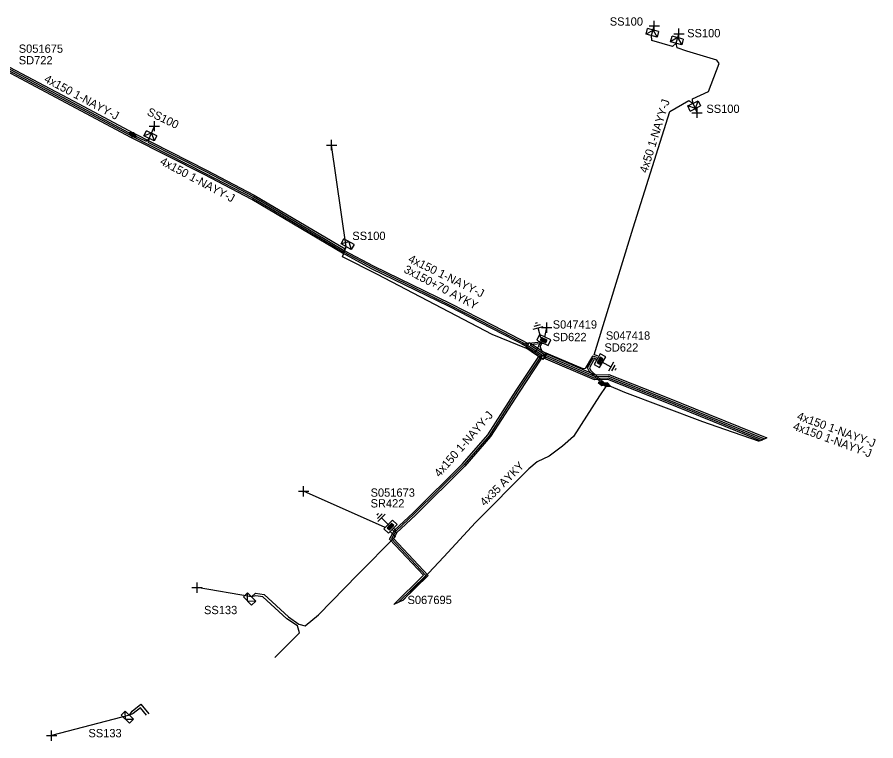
# Model space of a CAD drawing. Extents: x -737417 to -734469, y -1145580 to -1142703.
# Drawn here: x -736452.8 to -736349.1, y -1144284.4 to -1144197 of the extents above; entities that cross this region are included whole.
import ezdxf

# ---------------------------------------------------------------- set-up
doc = ezdxf.new("R2010")
doc.units = 0
for name, color, linetype in [('Vrstva 1', 7, 'Continuous'), ('Vrstva 14', 7, 'Continuous'), ('Vrstva 15', 7, 'Continuous'), ('Vrstva 19', 7, 'Continuous'), ('Vrstva 20', 7, 'Continuous'), ('Vrstva 28', 7, 'Continuous'), ('Vrstva 29', 7, 'Continuous'), ('Vrstva 30', 7, 'Continuous'), ('Vrstva 31', 7, 'Continuous'), ('Vrstva 33', 7, 'Continuous'), ('Vrstva 34', 7, 'Continuous'), ('Vrstva 4', 7, 'Continuous'), ('Vrstva 5', 7, 'Continuous'), ('Vrstva 59', 7, 'Continuous'), ('Vrstva 6', 7, 'Continuous'), ('Vrstva 8', 7, 'Continuous'), ('Vrstva 9', 7, 'Continuous')]:
    doc.layers.add(name, color=color, linetype=linetype)

# ---------------------------------------------------------------- blocks, each defined once
blk = doc.blocks.new('NN870')
at = {"layer": 'Vrstva 4'}
for points in [[(0, -0.25), (0.5, 0), (0, 0.25), (-0.5, 0), (0, -0.25)], [(0.37, 0), (0, 0.19), (-0.36, 0), (0, -0.19), (0.37, 0)], [(0.24, 0), (0, 0.12), (-0.25, 0), (0, -0.12), (0.24, 0)], [(0.12, 0), (0, 0.06), (-0.13, 0), (0, -0.06), (0.12, 0)]]:
    blk.add_lwpolyline(points, dxfattribs=at)
blk = doc.blocks.new('NN800')
at = {"layer": 'Vrstva 1'}
for points in [[(-0.44, 0.44), (0.44, -0.44)], [(-0.44, -0.44), (0.44, 0.44)]]:
    blk.add_lwpolyline(points, dxfattribs=at)
blk = doc.blocks.new('NN620')
at = {"layer": 'Vrstva 8'}
for points in [[(0.75, 0), (-0.75, 0)], [(-0.75, 0), (-0.75, -0.75)], [(0.75, -0.75), (0.75, 0)], [(-0.75, -0.75), (0.75, -0.75)], [(0.37, -0.18), (-0.38, -0.18)], [(-0.38, -0.18), (-0.38, -0.56)], [(-0.38, -0.56), (0.37, -0.56)], [(0.32, -0.23), (-0.33, -0.23)], [(-0.33, -0.23), (-0.33, -0.51)], [(-0.33, -0.51), (0.32, -0.51)], [(0.27, -0.27), (-0.28, -0.27)], [(-0.28, -0.27), (-0.28, -0.46)], [(-0.28, -0.46), (0.27, -0.46)], [(0.23, -0.32), (-0.23, -0.32)], [(-0.23, -0.32), (-0.23, -0.42)], [(-0.23, -0.42), (0.23, -0.42)], [(-0.19, -0.37), (0.19, -0.37)], [(0.23, -0.42), (0.23, -0.32)], [(0.27, -0.46), (0.27, -0.27)], [(0.32, -0.51), (0.32, -0.23)], [(0.37, -0.56), (0.37, -0.18)]]:
    blk.add_lwpolyline(points, dxfattribs=at)
blk = doc.blocks.new('NN630')
at = {"layer": 'Vrstva 9'}
for points in [[(0, -0.7), (-0.7, 0)], [(-0.7, -0.7), (-0.7, 0), (0.7, 0), (0.7, -0.7)], [(-0.7, -0.7), (0.7, -0.7)], [(0, -0.7), (0.7, 0)]]:
    blk.add_lwpolyline(points, dxfattribs=at)
blk = doc.blocks.new('NN810')
at = {"layer": 'Vrstva 14'}
for points in [[(0, -0.64), (0, -1.89)], [(0.63, -1.89), (-0.62, -1.89)], [(0.39, -2.2), (-0.4, -2.2)], [(0, -2.52), (-0.12, -2.52)], [(0.14, -2.52), (0, -2.52)]]:
    blk.add_lwpolyline(points, dxfattribs=at)

msp = doc.modelspace()

# ---------------------------------------------------------------- linework, layer by layer
at = {"layer": 'Vrstva 20'}
for points in [[(-736438.71, -1144211.02), (-736429.92, -1144215.47), (-736424.15, -1144218.48), (-736413.18, -1144224.99), (-736413.48, -1144225.51), (-736424.45, -1144219), (-736430.2, -1144216.01), (-736438.99, -1144211.56), (-736446.3, -1144207.66), (-736455.4, -1144202.85), (-736455.12, -1144202.32), (-736446.02, -1144207.12)], [(-736409.78, -1144227.02), (-736400.45, -1144231.59), (-736395.26, -1144234.23), (-736391.05, -1144236.42), (-736391.23, -1144236.77), (-736395.44, -1144234.59), (-736400.62, -1144231.95), (-736409.97, -1144227.38), (-736413.47, -1144225.51), (-736413.29, -1144225.16)], [(-736390.92, -1144236.27), (-736388.86, -1144237.66), (-736389.31, -1144238.32), (-736391.36, -1144236.93)], [(-736363.01, -1144248.14), (-736374.5, -1144243.49), (-736381.43, -1144240.73), (-736383.05, -1144240.78), (-736389.16, -1144238.18), (-736388.92, -1144237.62), (-736382.93, -1144240.18), (-736381.33, -1144240.13), (-736374.28, -1144242.93), (-736362.25, -1144247.8)], [(-736392.51, -1144242.06), (-736389.79, -1144237.97), (-736389.11, -1144237.71), (-736388.97, -1144238.09), (-736389.53, -1144238.29), (-736392.17, -1144242.28), (-736395.6, -1144247.65), (-736398.7, -1144251.21), (-736404.69, -1144257.12), (-736406.95, -1144259.26), (-736407.23, -1144258.96), (-736404.97, -1144256.84), (-736399, -1144250.93), (-736395.92, -1144247.41)], [(-736407.3, -1144267.92), (-736403.7, -1144264.39), (-736407.83, -1144260.02), (-736407.27, -1144259.01), (-736406.92, -1144259.21), (-736407.33, -1144259.96), (-736403.14, -1144264.41), (-736406.25, -1144267.45)]]:
    msp.add_lwpolyline(points, close=True, dxfattribs=at)
at = {"layer": 'Vrstva 5'}
for points in [[(-736382.64, -1144237.9), (-736383.09, -1144237.77), (-736378.37, -1144222.43), (-736373.96, -1144208.39), (-736371.64, -1144207.07), (-736371.17, -1144207.4), (-736371.23, -1144206.85), (-736369.3, -1144205.98), (-736368.01, -1144202.58), (-736368.28, -1144202.19), (-736371.88, -1144201.09), (-736373.08, -1144200.7), (-736373.19, -1144200.15), (-736373.65, -1144200.55), (-736376.13, -1144199.83), (-736376.15, -1144199.23)], [(-736454.82, -1144202.04), (-736455.22, -1144202.72), (-736446.21, -1144207.48), (-736438.9, -1144211.38), (-736430.11, -1144215.83), (-736424.35, -1144218.83), (-736413.38, -1144225.34), (-736409.88, -1144227.2), (-736400.54, -1144231.77), (-736395.35, -1144234.41), (-736391.14, -1144236.6), (-736389.09, -1144237.99), (-736383.01, -1144240.58), (-736381.4, -1144240.53), (-736374.43, -1144243.3), (-736362.76, -1144248.02)], [(-736454.65, -1144202.15), (-736454.94, -1144202.65), (-736446.11, -1144207.3), (-736438.8, -1144211.2)], [(-736438.8, -1144211.2), (-736437.22, -1144211.96), (-736436.86, -1144211.64), (-736436.99, -1144212.09), (-736430.01, -1144215.65), (-736424.25, -1144218.65), (-736413.29, -1144225.16), (-736413.05, -1144224.72)], [(-736389.59, -1144236.22), (-736389.81, -1144236.74), (-736390.17, -1144237.45), (-736395.42, -1144235.33), (-736409.27, -1144228.06), (-736413.51, -1144225.95), (-736413.05, -1144224.72)], [(-736389.51, -1144236.25), (-736391.8, -1144236.48), (-736391.24, -1144236.77), (-736389.39, -1144238.03), (-736389.66, -1144238.13), (-736392.34, -1144242.17), (-736395.76, -1144247.53), (-736398.85, -1144251.07), (-736404.83, -1144256.98), (-736407.02, -1144259.04), (-736407.35, -1144258.71)], [(-736389.17, -1144236.41), (-736390.81, -1144236.58), (-736388.99, -1144237.81), (-736382.97, -1144240.38), (-736381.36, -1144240.33), (-736374.35, -1144243.12), (-736362.5, -1144247.91)], [(-736382.74, -1144238.08), (-736383.3, -1144237.92), (-736384.18, -1144239.4), (-736384.41, -1144239.47), (-736389.39, -1144237.36), (-736389.61, -1144236.78), (-736389.38, -1144236.31)], [(-736382.11, -1144241.24), (-736383.69, -1144239.75), (-736383.9, -1144239.32), (-736383.21, -1144238.15), (-736382.85, -1144238.25)], [(-736382.95, -1144238.43), (-736383.12, -1144238.39), (-736383.67, -1144239.33), (-736383.53, -1144239.63), (-736381.75, -1144241.3), (-736381.59, -1144241.37)], [(-736382.11, -1144241.24), (-736381.7, -1144241.61), (-736382.46, -1144242.7), (-736385.58, -1144247.62), (-736386.92, -1144248.81), (-736388.52, -1144249.99), (-736389.97, -1144250.67), (-736390.98, -1144251.53), (-736397.44, -1144258.02), (-736401.24, -1144262.15), (-736406.2, -1144267.42)], [(-736381.59, -1144241.37), (-736379.41, -1144242.28), (-736370.02, -1144245.83), (-736367.33, -1144246.76), (-736363.18, -1144248.21)], [(-736424.47, -1144267), (-736424.01, -1144266.54), (-736422.96, -1144266.71), (-736420.02, -1144269.42), (-736418.77, -1144270.27), (-736418, -1144270.49), (-736416.41, -1144269.18), (-736411.62, -1144264.31), (-736407.1, -1144259.71), (-736407.72, -1144259.09)], [(-736407.49, -1144258.85), (-736407.14, -1144259.2), (-736407.58, -1144259.99), (-736403.42, -1144264.4), (-736406.77, -1144267.68)], [(-736421.65, -1144274.32), (-736418.69, -1144271.32), (-736418.93, -1144270.51), (-736420.2, -1144269.66), (-736423.1, -1144266.99), (-736423.95, -1144266.86), (-736424.47, -1144267)], [(-736437.17, -1144281.26), (-736437.9, -1144280.38), (-736438.79, -1144281.06), (-736439.22, -1144281.27), (-736438.9, -1144280.8), (-736437.86, -1144279.96), (-736436.89, -1144281.13)]]:
    msp.add_lwpolyline(points, dxfattribs=at)
at = {"layer": 'Vrstva 59'}
for points in [[(-736376.15, -1144199.23), (-736375.83, -1144198.05)], [(-736373.19, -1144200.15), (-736372.86, -1144199)], [(-736371.17, -1144207.4), (-736370.67, -1144208.53)], [(-736436.86, -1144211.64), (-736436.22, -1144210.16)], [(-736413.05, -1144224.72), (-736414.81, -1144212.45)], [(-736389.06, -1144235.63), (-736388.82, -1144234.48)], [(-736408.32, -1144258.62), (-736418.19, -1144254.25)], [(-736424.47, -1144267), (-736431.06, -1144265.88)], [(-736439.22, -1144281.27), (-736448.63, -1144283.75)]]:
    msp.add_lwpolyline(points, dxfattribs=at)

# ---------------------------------------------------------------- block references
at = {"layer": 'Vrstva 15'}
for p, rotation in [((-736389.34, -1144236.33), -163.90808889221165), ((-736382.72, -1144238.29), 60.581447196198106), ((-736407.42, -1144258.78), -134.27031399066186)]:
    msp.add_blockref('NN810', p, dxfattribs=dict(at, rotation=rotation))
at = {"layer": 'Vrstva 19'}
for p, rotation in [((-736438.82, -1144211.2), -28.07777501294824), ((-736382.11, -1144241.24), -14.036244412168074), ((-736381.59, -1144241.37), -22.657177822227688)]:
    msp.add_blockref('NN870', p, dxfattribs=dict(at, rotation=rotation))
at = {"layer": 'Vrstva 28'}
for p, rotation in [((-736389.34, -1144236.33), 154.6760387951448), ((-736382.72, -1144238.29), 60.58144726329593), ((-736407.42, -1144258.78), -134.27031399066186)]:
    msp.add_blockref('NN620', p, dxfattribs=dict(at, rotation=rotation))
at = {"layer": 'Vrstva 31'}
for p, rotation in [((-736376.15, -1144199.23), 166.21766401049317), ((-736373.19, -1144200.15), 165.3389888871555), ((-736371.17, -1144207.4), 26.38345828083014), ((-736436.86, -1144211.64), 154.2115582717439), ((-736413.05, -1144224.72), 150.6136667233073), ((-736424.47, -1144267), -45.37996664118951), ((-736439.22, -1144281.27), -44.00844170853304)]:
    msp.add_blockref('NN630', p, dxfattribs=dict(at, rotation=rotation))
at = {"layer": 'Vrstva 34'}
for p, rotation in [((-736375.83, -1144198.05), 44.99999995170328), ((-736372.86, -1144199), 45), ((-736370.67, -1144208.53), 44.99999995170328), ((-736436.22, -1144210.16), 45), ((-736414.81, -1144212.45), 45), ((-736388.82, -1144234.48), 45), ((-736418.19, -1144254.25), 44.99999995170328), ((-736431.06, -1144265.88), 45), ((-736448.63, -1144283.75), 45)]:
    msp.add_blockref('NN800', p, dxfattribs=dict(at, rotation=rotation))

# ---------------------------------------------------------------- texts
at = {"layer": 'Vrstva 29'}
for s, p in [('S051675', (-736452.6, -1144201.3)), ('S047419', (-736388.1, -1144234.6)), ('S047418', (-736381.68, -1144235.94)), ('S051673', (-736410.1, -1144254.9)), ('S067695', (-736405.64, -1144267.86))]:
    msp.add_text(s, height=1, dxfattribs=at).set_placement(p)
at = {"layer": 'Vrstva 30'}
for s, p in [('SD722', (-736452.6, -1144202.7)), ('SD622', (-736388.1, -1144236.12)), ('SD622', (-736381.85, -1144237.38)), ('SR422', (-736410.1, -1144256.2))]:
    msp.add_text(s, height=1, dxfattribs=at).set_placement(p)
at = {"layer": 'Vrstva 33'}
for s, p in [('SS100', (-736381.21, -1144198.02)), ('SS100', (-736371.86, -1144199.43)), ('SS100', (-736369.54, -1144208.56)), ('SS100', (-736412.31, -1144223.9)), ('SS133', (-736430.22, -1144269.08)), ('SS133', (-736444.18, -1144283.95))]:
    msp.add_text(s, height=1, dxfattribs=at).set_placement(p)
msp.add_text('SS100', height=1, rotation=334.212, dxfattribs=at).set_placement((-736437.19, -1144208.77))
at = {"layer": 'Vrstva 6'}
for s, rotation, p in [('4x150 1-NAYY-J', 331.922, (-736449.62, -1144204.76)), ('4x50 1-NAYY-J', 72.562, (-736376.7, -1144215.89)), ('4x150 1-NAYY-J', 331.917, (-736435.63, -1144214.71)), ('4x150 1-NAYY-J', 333.928, (-736405.64, -1144226.51)), ('3x150+70 AYKY', 332.305, (-736406.18, -1144227.76)), ('4x150 1-NAYY-J', 48.883, (-736401.77, -1144252.61)), ('4x150 1-NAYY-J', 339.997, (-736358.68, -1144245.55)), ('4x150 1-NAYY-J', 339.991, (-736359.15, -1144246.78)), ('4x35 AYKY', 45.133, (-736396.3, -1144256.12))]:
    msp.add_text(s, height=1, rotation=rotation, dxfattribs=at).set_placement(p)

doc.saveas('drawing.dxf')
